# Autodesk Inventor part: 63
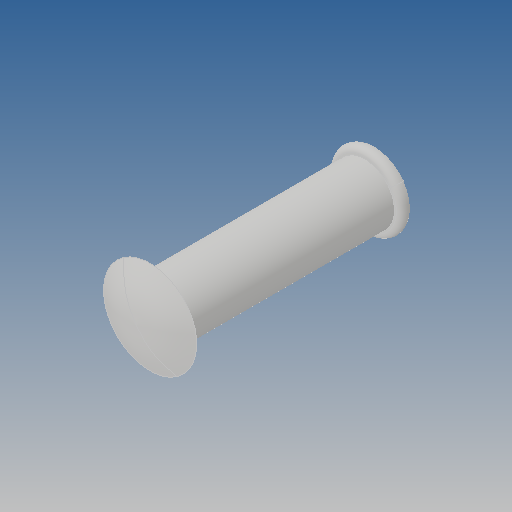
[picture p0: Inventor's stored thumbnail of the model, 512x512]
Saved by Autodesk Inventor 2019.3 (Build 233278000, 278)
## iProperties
Created: 2017-08
Part Number: 63
Material: Ogólny
Document SubType Name: Modeling
Designer: Admin
Density: 1 g/cm^3
Appearance: Domyślna
Author: Admin
Revision Number: ÈÎºÎ
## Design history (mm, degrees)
feature "ÊäÈë1"
node "Bryła1"
